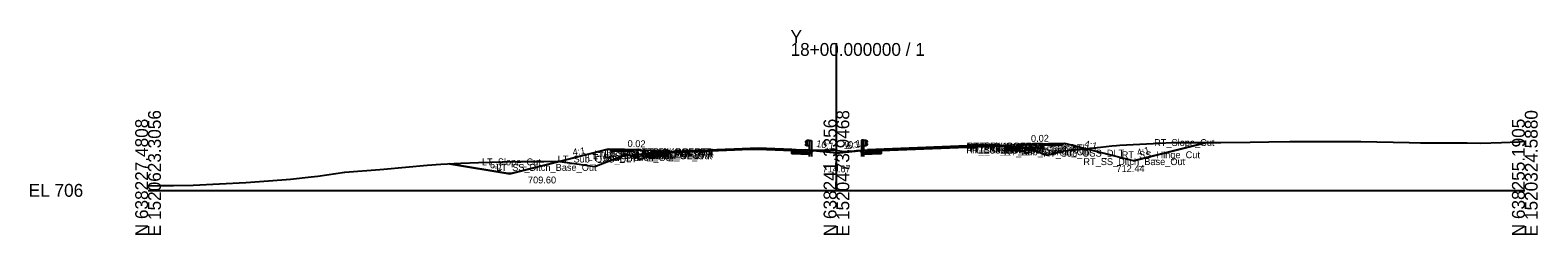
# Model space of a CAD drawing. Extents: x -26 to 303, y -10 to 5039.
# Drawn here: x -25.7 to 302.8, y 1490.3 to 1534.9 of the extents above; entities that cross this region are included whole.
import ezdxf

# ---------------------------------------------------------------- set-up
doc = ezdxf.new("R2010")
doc.units = 0
for name, color, linetype in [('Default', 7, 'Continuous'), ('Exist Cross Section Cell', 7, 'Continuous'), ('Exist XS Center Line Elevation Label', 7, 'Continuous'), ('Exist XS Ground Line', 7, 'Continuous'), ('Prop CMT Pvmt Course 1', 7, 'Continuous'), ('Prop CMT Pvmt Course 2', 7, 'Continuous'), ('Prop CMT Pvmt Course 3', 7, 'Continuous'), ('Prop CMT Pvmt Surface', 7, 'Continuous'), ('Prop CMT Pvmt Surface Shoulder', 7, 'Continuous'), ('Prop CMT Shld Paved Course 1', 7, 'Continuous'), ('Prop CMT Shld Paved Course 2', 7, 'Continuous'), ('Prop CMT Shld Paved Course 3', 7, 'Continuous'), ('Prop CMT Slope Grass', 7, 'Continuous'), ('Prop CMT Subgrade Earthwork', 7, 'Continuous'), ('Prop Conc 4in Sidewalk', 7, 'Continuous'), ('Prop XS Ditch Standard Text', 7, 'Continuous'), ('Prop XS Earthwork Shape', 7, 'Continuous'), ('Prop XS Side Slope Text', 7, 'Continuous'), ('Scratch_Level_0', 7, 'Continuous'), ('Typical Curb CELL', 7, 'Continuous'), ('Typical Guardrail CELL', 7, 'Continuous'), ('Typical Shoulder Slope Information CELL', 7, 'Continuous')]:
    doc.layers.add(name, color=color, linetype=linetype)

# ---------------------------------------------------------------- blocks, each defined once
blk = doc.blocks.new('2_6 CURB RIGHT')
at = {"layer": 'Typical Curb CELL'}
for p, q in [((0, -0.58), (0, 0)), ((0, 0), (1.75, -0.07)), ((2, 0.17), (2, 0.18)), ((2.5, 0.42), (2.24, 0.42)), ((2.31, 0.08), (2.33, -0.01)), ((2.46, 0.04), (2.31, 0.08)), ((2.33, -0.01), (2.46, 0.04)), ((2.5, -0.58), (2.5, 0.42)), ((2.5, -0.58), (0, -0.58)), ((0.26, -0.34), (0.35, -0.22)), ((0.38, -0.34), (0.26, -0.34)), ((0.35, -0.22), (0.38, -0.34)), ((1.03, -0.39), (1.09, -0.28)), ((1.19, -0.36), (1.03, -0.39)), ((1.09, -0.28), (1.19, -0.36)), ((1.51, -0.34), (1.6, -0.22)), ((1.63, -0.34), (1.51, -0.34)), ((1.6, -0.22), (1.63, -0.34)), ((2.27, -0.39), (2.34, -0.28)), ((2.44, -0.36), (2.27, -0.39)), ((2.34, -0.28), (2.44, -0.36))]:
    blk.add_line(p, q, dxfattribs=at)
for centre in [(2.27, 0.34), (2.43, 0.12), (2.49, 0.31), (0.01, -0.55), (0.02, -0.25), (0.03, -0.15), (0.07, -0.39), (0.09, -0.18), (0.17, -0.34), (0.2, -0.06), (0.22, -0.58), (0.3, -0.14), (0.34, -0.04), (0.38, -0.51), (0.49, -0.1), (0.52, -0.21), (0.59, -0.53), (0.67, -0.29), (0.69, -0.12), (0.7, -0.45), (0.71, -0.07), (0.76, -0.56), (0.79, -0.26), (0.93, -0.5), (0.97, -0.1), (1.09, -0.15), (1.11, -0.54), (1.26, -0.55), (1.27, -0.25), (1.28, -0.15), (1.32, -0.39), (1.34, -0.18), (1.42, -0.34), (1.45, -0.1), (1.47, -0.58), (1.54, -0.14), (1.63, -0.51), (1.74, -0.1), (1.77, -0.21), (1.84, -0.53), (1.92, -0.29), (1.94, -0.12), (1.95, -0.45), (1.96, -0.07), (2.01, -0.56), (2.04, -0.26), (2.18, -0.5), (2.22, -0.1), (2.34, -0.15), (2.35, -0.54)]:
    blk.add_circle(centre, 0.00802, dxfattribs=at)
for centre, start, end in [((1.76, 0.17), 267.6155, 0), ((2.24, 0.18), 90, 180)]:
    blk.add_arc(centre, 0.24, start, end, dxfattribs=at)

msp = doc.modelspace()

# ---------------------------------------------------------------- linework, layer by layer
at = {"layer": 'Exist Cross Section Cell'}
for p, q in [((150, 1500), (150, 1532.1)), ((0, 1500), (150, 1500)), ((150, 1500), (300, 1500))]:
    msp.add_line(p, q, dxfattribs=at)
at = {"layer": 'Exist XS Ground Line'}
msp.add_lwpolyline([(0, 1501.01), (2.32, 1501.03), (5.51, 1501.04), (9.8, 1501.12), (21.29, 1501.72), (26.24, 1502.05), (31.01, 1502.45), (35.54, 1502.91), (37, 1503.1), (42.89, 1503.94), (50.48, 1504.56), (51.41, 1504.65), (60.84, 1505.47), (63.82, 1505.69), (68.16, 1505.92), (71.98, 1506.08), (77.18, 1506.18), (81.33, 1506.25), (86.21, 1506.29), (89.26, 1506.35), (92.9, 1505.83), (97.36, 1505.18), (99.01, 1505.84), (103.13, 1507.45), (109.79, 1508.17), (110.8, 1508.27), (111.38, 1508.29), (112.4, 1508.32), (114.61, 1508.45), (115.05, 1508.46), (117.43, 1508.55), (118.8, 1508.62), (119.95, 1508.67), (121.33, 1508.74), (122.45, 1508.78), (124.08, 1508.86), (124.95, 1508.9), (125.72, 1508.94), (126.82, 1508.99), (127.45, 1508.99), (129.6, 1508.98), (129.95, 1508.98), (132.47, 1508.97), (133.41, 1508.96), (134.98, 1508.95), (137.15, 1508.92), (137.5, 1508.92), (138.35, 1508.91), (138.91, 1508.91), (140.26, 1508.88), (142.34, 1508.79), (145.68, 1508.76), (148.55, 1508.75), (150.27, 1508.66), (151.69, 1508.48), (152.74, 1508.51), (153.3, 1508.55), (154.38, 1508.66), (156.71, 1508.72), (160.4, 1508.86), (161.8, 1508.94), (162.98, 1508.98), (165.14, 1509.07), (165.62, 1509.09), (167.67, 1509.18), (169.35, 1509.26), (170.17, 1509.3), (171.63, 1509.36), (172.65, 1509.41), (173.74, 1509.47), (175.15, 1509.49), (176.63, 1509.52), (177.64, 1509.54), (179.4, 1509.59), (180.15, 1509.61), (182.17, 1509.65), (182.66, 1509.65), (184.86, 1509.69), (185.2, 1509.69), (185.54, 1509.69), (188.02, 1509.52), (190.95, 1509.32), (193.74, 1508.44), (195.98, 1507.66), (198.55, 1508.34), (199.58, 1508.6), (201.55, 1508.79), (207.52, 1509.4), (210.01, 1509.69), (211.02, 1509.78), (211.72, 1509.82), (220.46, 1510.3), (223.02, 1510.39), (233.3, 1510.44), (233.75, 1510.44), (240.18, 1510.5), (244.25, 1510.57), (248.8, 1510.62), (255.17, 1510.66), (263.18, 1510.65), (264.25, 1510.64), (274.78, 1510.43), (277.28, 1510.38), (277.86, 1510.38), (278.76, 1510.36), (287.44, 1510.35), (290.31, 1510.3), (294.93, 1510.43), (298.66, 1510.57), (300, 1510.7)], dxfattribs=at)
at = {"layer": 'Prop CMT Pvmt Course 1'}
for points in [[(113.25, 1508.38), (113.25, 1508.13)], [(113.25, 1508.13), (113.26, 1508.13)], [(113.26, 1508.13), (113.26, 1508.38)], [(114, 1508.41), (113.99, 1508.41)], [(139.19, 1508.84), (139.2, 1508.84)], [(140.25, 1508.66), (140.25, 1508.91)], [(159.75, 1508.66), (159.75, 1508.91)], [(186.74, 1509.62), (186.75, 1509.62)], [(186.74, 1509.37), (186.74, 1509.62)], [(186.75, 1509.37), (186.74, 1509.37)], [(186.75, 1509.62), (186.75, 1509.37)]]:
    msp.add_lwpolyline(points, dxfattribs=at)
at = {"layer": 'Prop CMT Pvmt Course 2'}
for points in [[(113.26, 1508.13), (113.25, 1508.13)], [(113.25, 1508.13), (113.25, 1507.88)], [(113.26, 1507.88), (113.26, 1508.13)], [(140.25, 1508.41), (140.25, 1508.66)], [(159.75, 1508.41), (159.75, 1508.66)], [(186.74, 1509.12), (186.74, 1509.37)], [(186.74, 1509.37), (186.75, 1509.37)], [(186.75, 1509.12), (186.74, 1509.12)], [(186.75, 1509.37), (186.75, 1509.12)], [(113.25, 1507.88), (113.26, 1507.88)]]:
    msp.add_lwpolyline(points, dxfattribs=at)
at = {"layer": 'Prop CMT Pvmt Course 3'}
for points in [[(140.25, 1508.04), (140.25, 1508.41)], [(140.26, 1508.04), (140.25, 1508.04)], [(159.74, 1508.04), (159.75, 1508.04)], [(159.75, 1508.04), (159.75, 1508.41)], [(186.74, 1509.12), (186.75, 1509.12)], [(186.74, 1508.75), (186.74, 1509.12)], [(186.75, 1508.75), (186.74, 1508.75)], [(186.75, 1509.12), (186.75, 1508.75)], [(113.26, 1507.88), (113.25, 1507.88)], [(113.25, 1507.88), (113.25, 1507.51)], [(113.25, 1507.51), (113.26, 1507.51)], [(113.26, 1507.51), (113.26, 1507.88)]]:
    msp.add_lwpolyline(points, dxfattribs=at)
at = {"layer": 'Prop CMT Pvmt Surface'}
for points in [[(114, 1508.41), (113.99, 1508.41)], [(139.19, 1508.84), (139.2, 1508.84)], [(186.74, 1509.62), (186.75, 1509.62)]]:
    msp.add_lwpolyline(points, dxfattribs=at)
at = {"layer": 'Prop CMT Pvmt Surface Shoulder'}
for points in [[(132.97, 1509.21), (112.25, 1508.34)], [(132.97, 1509.21), (143.25, 1508.79)], [(182.12, 1509.81), (156.75, 1508.79)], [(182.12, 1509.81), (187.75, 1509.58)]]:
    msp.add_lwpolyline(points, dxfattribs=at)
at = {"layer": 'Prop CMT Shld Paved Course 1'}
for p, q in [((132.97, 1508.96), (112.26, 1508.09)), ((132.97, 1508.96), (140.25, 1508.66)), ((143.51, 1508.53), (143.25, 1508.79)), ((156.49, 1508.53), (156.75, 1508.79))]:
    msp.add_line(p, q, dxfattribs=at)
for points in [[(112.25, 1508.09), (113.26, 1508.13)], [(113.25, 1508.13), (113.25, 1508.38)], [(159.73, 1508.66), (182.12, 1509.56)], [(186.01, 1509.65), (187.75, 1509.58)], [(186.75, 1509.37), (186.75, 1509.62)], [(187.75, 1509.33), (186.75, 1509.37)]]:
    msp.add_lwpolyline(points, dxfattribs=at)
at = {"layer": 'Prop CMT Shld Paved Course 2'}
for p, q in [((143.77, 1508.27), (143.51, 1508.53)), ((156.23, 1508.27), (156.49, 1508.53))]:
    msp.add_line(p, q, dxfattribs=at)
for points in [[(113.26, 1508.13), (112.25, 1508.09)], [(113.25, 1507.88), (113.25, 1508.13)], [(140.25, 1508.66), (143.51, 1508.53)], [(143.77, 1508.27), (140.25, 1508.41)], [(156.23, 1508.27), (159.75, 1508.41)], [(159.75, 1508.66), (156.49, 1508.53)], [(186.75, 1509.12), (186.75, 1509.37)], [(186.75, 1509.37), (187.75, 1509.33)], [(187.75, 1509.08), (186.75, 1509.12)], [(112.25, 1507.84), (113.26, 1507.88)]]:
    msp.add_lwpolyline(points, dxfattribs=at)
at = {"layer": 'Prop CMT Shld Paved Course 3'}
for p, q in [((144.16, 1507.88), (143.77, 1508.27)), ((155.84, 1507.88), (156.23, 1508.27)), ((109.25, 1507.76), (108.82, 1507.33)), ((109.75, 1507.76), (109.25, 1507.76))]:
    msp.add_line(p, q, dxfattribs=at)
for points in [[(140.25, 1508.41), (143.77, 1508.27)], [(144.16, 1507.88), (140.25, 1508.04)], [(155.84, 1507.88), (159.75, 1508.04)], [(159.75, 1508.41), (156.23, 1508.27)], [(186.75, 1508.75), (186.75, 1509.12)], [(186.75, 1509.12), (187.75, 1509.08)], [(191.18, 1508.57), (186.75, 1508.75)], [(108.82, 1507.33), (113.26, 1507.51)], [(113.26, 1507.88), (112.25, 1507.84)], [(113.25, 1507.51), (113.25, 1507.88)]]:
    msp.add_lwpolyline(points, dxfattribs=at)
at = {"layer": 'Prop CMT Slope Grass'}
for p, q in [((78.86, 1503.6), (100.25, 1508.95)), ((100.25, 1508.95), (109.75, 1508.76)), ((150, 1508.12), (143.25, 1508.79)), ((150, 1508.12), (156.75, 1508.79)), ((199.75, 1510.19), (190.25, 1510)), ((214.75, 1506.44), (199.75, 1510.19)), ((65.7, 1505.79), (78.86, 1503.6))]:
    msp.add_line(p, q, dxfattribs=at)
msp.add_lwpolyline([(214.75, 1506.44), (230.7, 1510.43)], dxfattribs=at)
at = {"layer": 'Prop CMT Subgrade Earthwork'}
for p, q in [((108.82, 1507.33), (107.35, 1508.8)), ((113.26, 1507.51), (113.26, 1508.38)), ((140.25, 1508.91), (140.25, 1508.04)), ((159.75, 1508.91), (159.75, 1508.04)), ((191.18, 1508.57), (192.65, 1510.05))]:
    msp.add_line(p, q, dxfattribs=at)
for points in [[(140.25, 1508.91), (140.25, 1508.04), (140.26, 1508.04)], [(140.25, 1508.04), (144.16, 1507.88)], [(144.16, 1507.88), (144.91, 1508.63)], [(155.84, 1507.88), (155.09, 1508.63)], [(159.75, 1508.04), (155.84, 1507.88)], [(159.75, 1508.91), (159.75, 1508.04), (159.74, 1508.04)], [(186.74, 1509.62), (186.74, 1508.75), (186.75, 1508.75)], [(186.75, 1508.75), (191.18, 1508.57)], [(113.26, 1507.51), (108.82, 1507.33)]]:
    msp.add_lwpolyline(points, dxfattribs=at)
at = {"layer": 'Prop Conc 4in Sidewalk'}
for p, q in [((100.75, 1508.94), (100.75, 1508.6)), ((100.75, 1508.6), (105.75, 1508.5)), ((105.75, 1508.84), (105.75, 1508.5)), ((194.25, 1510.08), (194.25, 1509.75)), ((199.25, 1509.85), (194.25, 1509.75)), ((199.25, 1510.18), (199.25, 1509.85))]:
    msp.add_line(p, q, dxfattribs=at)
at = {"layer": 'Prop XS Earthwork Shape'}
for points in [[(97.36, 1505.18), (99.01, 1505.84), (103.13, 1507.45), (108.15, 1508), (107.35, 1508.8), (100.25, 1508.95), (89.64, 1506.29), (92.9, 1505.83)], [(113.26, 1507.51), (113.26, 1508.37), (112.4, 1508.32), (111.38, 1508.29), (110.8, 1508.27), (109.79, 1508.17), (108.15, 1508), (108.82, 1507.33)], [(113.26, 1508.37), (113.99, 1508.41), (113.26, 1508.38)], [(113.99, 1508.41), (114.61, 1508.45), (115.05, 1508.46), (116.5, 1508.52), (114, 1508.41)], [(116.5, 1508.52), (118.19, 1508.59), (117.43, 1508.55)], [(118.19, 1508.59), (118.8, 1508.62), (119.95, 1508.67), (121.33, 1508.74), (122.45, 1508.78), (124.08, 1508.86), (124.95, 1508.9), (125.72, 1508.94), (126.82, 1508.99), (127.45, 1508.99), (127.74, 1508.99)], [(134.98, 1508.95), (137.15, 1508.92), (137.5, 1508.92), (138.35, 1508.91), (138.91, 1508.91), (140.25, 1508.88), (140.25, 1508.91), (132.97, 1509.21), (127.74, 1508.99), (129.6, 1508.98), (129.95, 1508.98), (132.47, 1508.97), (133.41, 1508.96)], [(142.34, 1508.79), (143.4, 1508.78), (144.91, 1508.63), (144.16, 1507.88), (140.26, 1508.04), (140.25, 1508.88), (140.26, 1508.88)], [(148.55, 1508.75), (150.27, 1508.66), (151.69, 1508.48), (152.74, 1508.51), (153.3, 1508.55), (154.38, 1508.66), (155.73, 1508.69), (155.09, 1508.63), (150, 1508.12), (144.91, 1508.63), (143.4, 1508.78), (145.68, 1508.76)], [(159.75, 1508.83), (159.74, 1508.04), (155.84, 1507.88), (155.09, 1508.63), (155.73, 1508.69), (156.71, 1508.72)], [(172.65, 1509.41), (173.74, 1509.47), (175.15, 1509.49), (176.63, 1509.52), (177.64, 1509.54), (179.4, 1509.59), (180.15, 1509.61), (182.17, 1509.65), (182.66, 1509.65), (184.86, 1509.69), (185.2, 1509.69), (182.12, 1509.81), (159.75, 1508.91), (159.75, 1508.83), (160.4, 1508.86), (161.8, 1508.94), (162.98, 1508.98), (165.14, 1509.07), (165.62, 1509.09), (167.67, 1509.18), (169.35, 1509.26), (170.17, 1509.3), (171.63, 1509.36)], [(185.54, 1509.69), (186, 1509.65), (185.2, 1509.69)], [(186, 1509.65), (186.74, 1509.6), (186.74, 1509.62)], [(186.74, 1509.6), (188.02, 1509.52), (190.95, 1509.32), (191.69, 1509.09), (191.18, 1508.57), (186.75, 1508.75)], [(198.55, 1508.34), (199.58, 1508.6), (201.55, 1508.79), (204.25, 1509.07), (199.75, 1510.19), (192.65, 1510.05), (191.69, 1509.09), (193.74, 1508.44), (195.98, 1507.66)], [(211.72, 1509.82), (220.46, 1510.3), (223.02, 1510.39), (230.7, 1510.43), (214.75, 1506.44), (204.25, 1509.07), (207.52, 1509.4), (210.01, 1509.69), (211.02, 1509.78)], [(77.18, 1506.18), (81.33, 1506.25), (86.21, 1506.29), (89.26, 1506.35), (89.64, 1506.29), (78.86, 1503.6), (65.7, 1505.79), (68.16, 1505.92), (71.98, 1506.08)]]:
    msp.add_lwpolyline(points, close=True, dxfattribs=at)
at = {"layer": 'Typical Guardrail CELL'}
for p, q in [((143.57, 1510.86), (143.28, 1510.66)), ((143.57, 1510.33), (143.28, 1510.53)), ((143.57, 1510.23), (143.28, 1510.03)), ((143.57, 1509.7), (143.28, 1509.9)), ((144.07, 1510.86), (143.57, 1510.86)), ((143.57, 1510.86), (143.57, 1509.7)), ((143.57, 1510.28), (143.57, 1510.33)), ((143.57, 1510.28), (143.57, 1510.23)), ((144.07, 1509.7), (143.57, 1509.7)), ((144.07, 1510.86), (144.07, 1508.38)), ((144.07, 1510.86), (144.57, 1510.86)), ((144.07, 1508.38), (144.57, 1508.38)), ((144.07, 1508.38), (144.07, 1507.37)), ((144.57, 1510.86), (144.57, 1508.38)), ((144.57, 1508.38), (144.57, 1507.37)), ((155.93, 1510.9), (155.43, 1510.9)), ((155.43, 1510.9), (155.43, 1508.41)), ((155.93, 1508.41), (155.43, 1508.41)), ((155.43, 1508.41), (155.43, 1507.41)), ((155.93, 1510.9), (155.93, 1508.41)), ((155.93, 1510.9), (156.43, 1510.9)), ((155.93, 1509.74), (156.43, 1509.74)), ((155.93, 1508.41), (155.93, 1507.41)), ((156.43, 1510.9), (156.43, 1509.74)), ((156.43, 1510.9), (156.72, 1510.7)), ((156.43, 1510.37), (156.72, 1510.57)), ((156.43, 1510.32), (156.43, 1510.37)), ((156.43, 1510.32), (156.43, 1510.27)), ((156.43, 1510.27), (156.72, 1510.07)), ((156.43, 1509.74), (156.72, 1509.94))]:
    msp.add_line(p, q, dxfattribs=at)
for centre, start, end in [((143.33, 1510.59), 125.003, 235.0112), ((143.33, 1509.97), 125.0059, 235.0366), ((156.67, 1510.63), 304.9888, 54.997), ((156.67, 1510.01), 304.9634, 54.9941)]:
    msp.add_arc(centre, 0.0776, start, end, dxfattribs=at)

# ---------------------------------------------------------------- block references
at = {"layer": 'Prop CMT Slope Grass', "yscale": -1, "rotation": 180}
msp.add_blockref('2_6 CURB RIGHT', (112.25, 1508.34), dxfattribs=at)
at = {"layer": 'Prop CMT Slope Grass'}
msp.add_blockref('2_6 CURB RIGHT', (187.75, 1509.58), dxfattribs=at)

# ---------------------------------------------------------------- texts
at = {"layer": 'Default'}
msp.add_text('-', height=0.0001, dxfattribs=at).set_placement((0, 1500))
at = {"layer": 'Exist Cross Section Cell'}
for s, p in [('Y', (140, 1532.1)), ('18+00.000000 / 1', (140, 1529.3)), ('EL 706', (-26, 1498.6))]:
    msp.add_text(s, height=2.8, dxfattribs=at).set_placement(p)
for s, p in [('N 638227.4808', (0, 1490)), ('E 1520623.3056', (2.8, 1490)), ('N 638241.3356', (150, 1490)), ('E 1520473.9468', (152.8, 1490)), ('N 638255.1905', (300, 1490)), ('E 1520324.5880', (302.8, 1490))]:
    msp.add_text(s, height=2.8, rotation=90, dxfattribs=at).set_placement(p)
at = {"layer": 'Exist XS Center Line Elevation Label'}
msp.add_text('714.67', height=1.5, dxfattribs=at).set_placement((146.95, 1503.92))
at = {"layer": 'Prop XS Ditch Standard Text'}
for s, p in [('712.44', (211.01, 1504)), ('709.60', (82.78, 1501.51))]:
    msp.add_text(s, height=1.5, dxfattribs=at).set_placement(p)
at = {"layer": 'Prop XS Side Slope Text'}
for s, rotation, p in [('4:1', 9.4623, (92.63, 1507.52)), ('10:1', 350.5377, (145.51, 1509.49)), ('10:1', 9.4623, (151.61, 1508.95)), ('6:1', 9.4623, (152.4, 1508.91)), ('4:1', 346.7942, (203.91, 1509.49)), ('4:1', 14.0362, (215.67, 1507.44)), ('6:1', 350.5191, (74.42, 1504.89))]:
    msp.add_text(s, height=1.5, rotation=rotation, dxfattribs=at).set_placement(p)
at = {"layer": 'Scratch_Level_0'}
for s, p in [('LT_Sub_Trench_Out', (95.74, 1506.39)), ('LT_PS3_Shelf_Out', (96.95, 1506.78)), ('LT_GS_OS_CTL', (97.19, 1507.24)), ('LT_PS3_OEOP', (99.15, 1506.8)), ('LT_PS2_OEOP', (99.41, 1507.07)), ('LT_PS1_OEOP', (99.85, 1507.33)), ('LT_PV2_PGL_Out', (106.36, 1507.41)), ('LT_PV3_PGL_Out', (106.36, 1507.16)), ('LT_Sub_PGL_Out', (106.4, 1506.79)), ('LT_Sub_Out_DLT', (106.49, 1507.66)), ('LT_PV1_PGL_Out', (106.54, 1507.66)), ('LT_PV2_OEOT', (107.61, 1507.41)), ('LT_PV3_OEOT', (107.61, 1507.16)), ('LT_Sub_OEOT', (107.64, 1506.79)), ('LT_PV1_OEOT', (107.79, 1507.66)), ('RT_PV2_PGL_Out', (178.27, 1508.65)), ('RT_PV3_PGL_Out', (178.27, 1508.4)), ('RT_Sub_PGL_Out', (178.31, 1508.03)), ('RT_Sub_Out_DLT', (178.37, 1508.91)), ('RT_PV1_PGL_Out', (178.45, 1508.9)), ('RT_PV2_OEOT', (179.54, 1508.65)), ('RT_PV3_OEOT', (179.54, 1508.4)), ('RT_Sub_OEOT', (179.57, 1508.03)), ('RT_PV1_OEOT', (179.72, 1508.9)), ('RT_Sub_Trench_Out', (186.5, 1507.65)), ('RT_PS3_Shelf_Out', (186.93, 1508.04)), ('RT_PS1_OEOP', (187.78, 1508.58)), ('RT_PS2_OEOP', (187.86, 1508.32)), ('RT_PS3_OEOP', (188.12, 1508.06)), ('RT_GS_OS_CTL', (189.12, 1508.5)), ('RT_Sub_OSS_DLT', (195.1, 1507.35)), ('RT_SS_Hinge_Cut', (212.16, 1507)), ('RT_Slope_Cut', (219.22, 1509.65)), ('LT_Slope_Cut', (72.75, 1505.45)), ('LT_SS_Ditch_Base_Out', (75.88, 1504.24)), ('LT_Sub_OSS_DLT', (89.25, 1506.07)), ('RT_SS_Ditch_Base_Out', (203.81, 1505.5))]:
    msp.add_text(s, height=1.5, dxfattribs=at).set_placement(p)
at = {"layer": 'Typical Shoulder Slope Information CELL'}
for rotation, p in [(1.1403, (192.4, 1510.53)), (358.8597, (104.48, 1509.45))]:
    msp.add_text('0.02', height=1.5, rotation=rotation, dxfattribs=at).set_placement(p)

doc.saveas('drawing.dxf')
